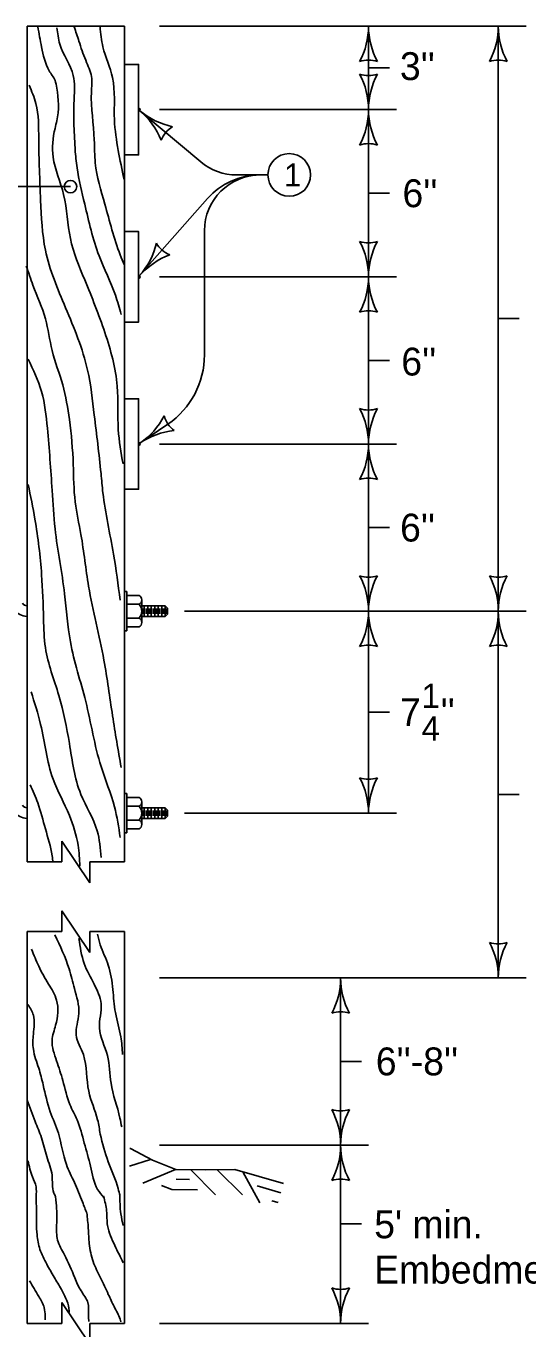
# Model space of a CAD drawing. Extents: x 228 to 3572, y -1307 to 1277.
# Drawn here: x 1403 to 1691, y -892 to -144 of the extents above; entities that cross this region are included whole.
import ezdxf

# ---------------------------------------------------------------- set-up
doc = ezdxf.new("R2010")
doc.units = 0
for name, color, linetype in [('dsnStdDimension', 7, 'Continuous'), ('Level 2', 7, 'Continuous'), ('Level 3', 7, 'Continuous')]:
    doc.layers.add(name, color=color, linetype=linetype)

msp = doc.modelspace()

# ---------------------------------------------------------------- linework, layer by layer
at = {"layer": 'dsnStdDimension'}
for p, q in [((1479.6, -143.79), (1690.1, -143.79)), ((1599.6, -143.79), (1599.6, -191.79)), ((1674.1, -143.79), (1674.1, -479.78)), ((1611.6, -167.79), (1599.6, -167.79)), ((1468.31, -192.38), (1503.31, -221.79)), ((1479.6, -191.79), (1615.6, -191.79)), ((1599.6, -191.79), (1599.6, -287.78)), ((1523.89, -229.29), (1541.87, -229.29)), ((1346.37, -235.99), (1428.56, -235.99)), ((1468.23, -287.06), (1507.17, -242.86)), ((1611.6, -239.79), (1599.6, -239.79)), ((1505.45, -261.29), (1505.45, -332.64)), ((1479.6, -287.78), (1615.6, -287.78)), ((1599.6, -287.78), (1599.6, -383.78)), ((1686.1, -311.78), (1674.1, -311.78)), ((1611.6, -335.78), (1599.6, -335.78)), ((1468.35, -383.27), (1484.44, -372.33)), ((1479.6, -383.78), (1615.6, -383.78)), ((1599.6, -383.78), (1599.6, -479.78)), ((1611.6, -431.78), (1599.6, -431.78)), ((1494.05, -479.78), (1690.1, -479.78)), ((1599.6, -479.78), (1599.6, -595.78)), ((1674.1, -479.78), (1674.1, -690.3)), ((1611.6, -537.78), (1599.6, -537.78)), ((1686.1, -585.04), (1674.1, -585.04)), ((1494.05, -595.78), (1615.6, -595.78)), ((1479.6, -690.3), (1690.1, -690.3)), ((1583.6, -690.3), (1583.6, -786.3)), ((1595.6, -738.3), (1583.6, -738.3)), ((1479.6, -786.3), (1599.6, -786.3)), ((1583.6, -786.3), (1583.6, -888.72)), ((1595.6, -831.51), (1583.6, -831.51)), ((1479.6, -888.72), (1599.6, -888.72))]:
    msp.add_line(p, q, dxfattribs=at)
msp.add_circle((1428.56, -235.99), 3.56, dxfattribs=at)
for centre, radius, start, end in [((1556.42, -143.79), 43.18, 331.92751, 0), ((1642.78, -143.79), 43.18, 180, 208.07249), ((1630.92, -143.79), 43.18, 331.92751, 0), ((1717.28, -143.79), 43.18, 180, 208.07249), ((1599.6, -179.99), 16.68, 72.26665, 107.73335), ((1674.1, -179.99), 16.68, 72.26665, 107.73335), ((1599.6, -155.58), 16.68, 252.26665, 287.73335), ((1556.42, -191.79), 43.18, 0, 28.07249), ((1642.78, -191.79), 43.18, 151.92751, 180), ((1496.08, -159.32), 43.18, 229.96145, 258.03394), ((1440.53, -225.44), 43.18, 21.88896, 49.96145), ((1556.42, -191.79), 43.18, 331.92751, 0), ((1642.78, -191.79), 43.18, 180, 208.07249), ((1496.03, -215.67), 16.68, 122.2281, 157.6948), ((1599.6, -227.99), 16.68, 72.26665, 107.73335), ((1523.9, -197.29), 32, 229.96456, 270), ((1537.45, -261.29), 32, 90, 180), ((1537.19, -269.29), 40, 90, 138.62574), ((1435.83, -258.52), 43.18, 318.62652, 346.69901), ((1492.16, -259.9), 16.68, 210.89317, 246.35987), ((1599.6, -251.58), 16.68, 252.26665, 287.73335), ((1556.42, -287.78), 43.18, 0, 28.07249), ((1642.78, -287.78), 43.18, 151.92751, 180), ((1500.63, -315.61), 43.18, 110.55403, 138.62652), ((1556.42, -287.78), 43.18, 331.92751, 0), ((1642.78, -287.78), 43.18, 180, 208.07249), ((1599.6, -323.99), 16.68, 72.26665, 107.73335), ((1457.45, -332.64), 48, 304.20895, 0), ((1599.6, -347.58), 16.68, 252.26665, 287.73335), ((1556.42, -383.78), 43.18, 0, 28.07249), ((1642.78, -383.78), 43.18, 151.92751, 180), ((1444.07, -347.57), 43.18, 304.20947, 332.28196), ((1498.29, -362.92), 16.68, 196.47612, 231.94282), ((1492.62, -418.98), 43.18, 96.13698, 124.20947), ((1556.42, -383.78), 43.18, 331.92751, 0), ((1642.78, -383.78), 43.18, 180, 208.07249), ((1599.6, -419.99), 16.68, 72.26665, 107.73335), ((1599.6, -443.58), 16.68, 252.26665, 287.73335), ((1556.42, -479.78), 43.18, 0, 28.07249), ((1642.78, -479.78), 43.18, 151.92751, 180), ((1674.1, -443.58), 16.68, 252.26665, 287.73335), ((1630.92, -479.78), 43.18, 0, 28.07249), ((1717.28, -479.78), 43.18, 151.92751, 180), ((1556.42, -479.78), 43.18, 331.92751, 0), ((1642.78, -479.78), 43.18, 180, 208.07249), ((1630.92, -479.78), 43.18, 331.92751, 0), ((1717.28, -479.78), 43.18, 180, 208.07249), ((1599.6, -515.99), 16.68, 72.26665, 107.73335), ((1674.1, -515.99), 16.68, 72.26665, 107.73335), ((1599.6, -559.58), 16.68, 252.26665, 287.73335), ((1556.42, -595.78), 43.18, 0, 28.07249), ((1642.78, -595.78), 43.18, 151.92751, 180), ((1674.1, -654.09), 16.68, 252.26665, 287.73335), ((1630.92, -690.3), 43.18, 0, 28.07249), ((1717.28, -690.3), 43.18, 151.92751, 180), ((1540.42, -690.3), 43.18, 331.92751, 0), ((1626.78, -690.3), 43.18, 180, 208.07249), ((1583.6, -726.51), 16.68, 72.26665, 107.73335), ((1583.6, -750.09), 16.68, 252.26665, 287.73335), ((1540.42, -786.3), 43.18, 0, 28.07249), ((1626.78, -786.3), 43.18, 151.92751, 180), ((1540.42, -786.3), 43.18, 331.92751, 0), ((1626.78, -786.3), 43.18, 180, 208.07249), ((1583.6, -822.51), 16.68, 72.26665, 107.73335), ((1583.6, -852.52), 16.68, 252.26665, 287.73335), ((1540.42, -888.72), 43.18, 0, 28.07249), ((1626.78, -888.72), 43.18, 151.92751, 180)]:
    msp.add_arc(centre, radius, start, end, dxfattribs=at)
at = {"layer": 'Level 2'}
for p, q in [((1403.6, -143.79), (1459.6, -143.79)), ((1403.6, -143.79), (1403.6, -623.78)), ((1459.6, -143.79), (1459.6, -623.78)), ((1459.6, -217.79), (1467.6, -217.79)), ((1459.6, -468.45), (1459.6, -491.12)), ((1460.93, -468.45), (1459.6, -468.45)), ((1460.93, -468.45), (1460.93, -491.12)), ((1460.93, -470.78), (1467.93, -470.78)), ((1403.59, -476.77), (1403.61, -482.8)), ((1460.93, -475.78), (1467.93, -475.78)), ((1469.43, -475.78), (1469.43, -473.28)), ((1469.43, -483.78), (1469.43, -475.78)), ((1469.43, -476.78), (1482.91, -476.78)), ((1469.91, -481.28), (1469.91, -478.28)), ((1470.91, -482.28), (1470.91, -477.28)), ((1471.91, -481.28), (1471.91, -478.28)), ((1472.91, -482.28), (1472.91, -477.28)), ((1473.91, -481.28), (1473.91, -478.28)), ((1474.91, -482.28), (1474.91, -477.28)), ((1475.91, -481.28), (1475.91, -478.28)), ((1476.91, -482.28), (1476.91, -477.28)), ((1477.91, -481.28), (1477.91, -478.28)), ((1478.91, -482.28), (1478.91, -477.28)), ((1479.91, -481.28), (1479.91, -478.28)), ((1480.91, -482.28), (1480.91, -477.28)), ((1481.91, -481.28), (1481.91, -478.28)), ((1482.91, -476.78), (1484.16, -478.03)), ((1482.91, -482.28), (1482.91, -477.28)), ((1483.91, -481.28), (1483.91, -478.28)), ((1484.16, -481.53), (1484.16, -478.03)), ((1460.93, -483.78), (1467.93, -483.78)), ((1469.43, -482.78), (1482.91, -482.78)), ((1469.43, -486.28), (1469.43, -483.78)), ((1482.91, -482.78), (1484.16, -481.53)), ((1460.93, -491.12), (1459.6, -491.12)), ((1460.93, -488.78), (1467.93, -488.78)), ((1459.6, -584.45), (1459.6, -607.12)), ((1460.93, -584.45), (1459.6, -584.45)), ((1460.93, -584.45), (1460.93, -607.12)), ((1460.93, -586.78), (1467.93, -586.78)), ((1469.43, -591.78), (1469.43, -589.28)), ((1460.93, -591.78), (1467.93, -591.78)), ((1469.43, -599.78), (1469.43, -591.78)), ((1469.43, -592.78), (1482.91, -592.78)), ((1469.91, -597.28), (1469.91, -594.28)), ((1470.91, -598.28), (1470.91, -593.28)), ((1471.91, -597.28), (1471.91, -594.28)), ((1472.91, -598.28), (1472.91, -593.28)), ((1473.91, -597.28), (1473.91, -594.28)), ((1474.91, -598.28), (1474.91, -593.28)), ((1475.91, -597.28), (1475.91, -594.28)), ((1476.91, -598.28), (1476.91, -593.28)), ((1477.91, -597.28), (1477.91, -594.28)), ((1478.91, -598.28), (1478.91, -593.28)), ((1479.91, -597.28), (1479.91, -594.28)), ((1480.91, -598.28), (1480.91, -593.28)), ((1481.91, -597.28), (1481.91, -594.28)), ((1482.91, -592.78), (1484.16, -594.03)), ((1482.91, -598.28), (1482.91, -593.28)), ((1482.91, -598.78), (1484.16, -597.53)), ((1483.91, -597.28), (1483.91, -594.28)), ((1484.16, -597.53), (1484.16, -594.03)), ((1460.93, -599.78), (1467.93, -599.78)), ((1460.93, -604.78), (1467.93, -604.78)), ((1469.43, -598.78), (1482.91, -598.78)), ((1469.43, -602.28), (1469.43, -599.78)), ((1423.6, -623.78), (1423.6, -611.78)), ((1439.6, -635.78), (1423.6, -611.78)), ((1460.93, -607.12), (1459.6, -607.12)), ((1423.6, -623.78), (1403.6, -623.78)), ((1439.6, -623.78), (1439.6, -635.78)), ((1459.6, -623.78), (1439.6, -623.78)), ((1423.6, -663.78), (1423.6, -651.78)), ((1439.6, -675.78), (1423.6, -651.78)), ((1403.6, -663.78), (1403.6, -816.25)), ((1423.6, -663.78), (1403.6, -663.78)), ((1439.6, -663.78), (1439.6, -675.78)), ((1459.6, -663.78), (1439.6, -663.78)), ((1459.6, -663.78), (1459.6, -816.25)), ((1474.39, -794.68), (1462.37, -798.41)), ((1488.73, -800.31), (1470.05, -808.31)), ((1497.49, -800.43), (1511.77, -814.89)), ((1512.89, -800.67), (1527.34, -814.96)), ((1527.44, -801.68), (1537.3, -819.45)), ((1403.6, -816.25), (1403.6, -888.72)), ((1459.6, -816.25), (1459.6, -888.72)), ((1423.6, -888.72), (1423.6, -876.72)), ((1439.6, -900.72), (1423.6, -876.72)), ((1423.6, -888.72), (1403.6, -888.72)), ((1439.6, -888.72), (1439.6, -900.72)), ((1459.6, -888.72), (1439.6, -888.72))]:
    msp.add_line(p, q, dxfattribs=at)
for points in [[(1459.6, -165.79), (1467.6, -165.79), (1467.6, -217.79), (1459.6, -217.79)], [(1459.6, -261.78), (1467.6, -261.78), (1467.6, -313.78), (1459.6, -313.78)], [(1459.6, -357.78), (1467.6, -357.78), (1467.6, -409.78), (1459.6, -409.78)]]:
    msp.add_lwpolyline(points, close=True, dxfattribs=at)
for points in [[(1462.67, -788.22), (1462.91, -788.38), (1475.61, -795.06), (1488.91, -800.38), (1505.91, -800.48), (1522.9, -800.38), (1536.89, -804.39), (1550.89, -808.39)], [(1489.21, -805.97), (1496.94, -806.02)], [(1489.21, -805.97), (1496.94, -806.02)], [(1480.72, -809.53), (1486.65, -811.91), (1501.43, -811.99)], [(1480.72, -809.53), (1486.65, -811.91), (1501.43, -811.99)], [(1535.67, -809.82), (1549.36, -813.74)], [(1544.03, -818.34), (1547.74, -819.4)]]:
    msp.add_lwpolyline(points, dxfattribs=at)
msp.add_circle((1554.12, -229.29), 12.25, dxfattribs=at)
for centre, radius, start, end in [((1466.6, -473.28), 2.83, 298.07249, 61.92751), ((1404.12, -472.78), 4.02, 217.44554, 262.43895), ((1463.35, -479.78), 6.08, 318.88791, 41.11209), ((1404.12, -472.78), 10.04, 217.30891, 267.0982), ((1466.6, -486.28), 2.83, 298.07249, 61.92751), ((1466.6, -589.28), 2.83, 298.07249, 61.92751), ((1404.12, -588.78), 10.04, 217.30891, 267.0982), ((1404.12, -588.78), 4.02, 217.44554, 262.43895), ((1463.35, -595.78), 6.08, 318.88791, 41.11209), ((1466.6, -602.28), 2.83, 298.07249, 61.92751)]:
    msp.add_arc(centre, radius, start, end, dxfattribs=at)
for points in [[(1409.75, -144.19), (1411.95, -155.76), (1416.35, -169.52), (1419.65, -175.03), (1420.75, -179.43), (1420.75, -198.15), (1419.65, -202.55), (1418.55, -219.07), (1424.61, -240.54), (1428.46, -265.86), (1436.71, -289.54), (1448.26, -319.82), (1455.41, -350.65), (1455.96, -375.42), (1458.71, -395.24)], [(1420.75, -144.75), (1422.41, -154.1), (1430.11, -172.27), (1430.66, -185.49), (1431.21, -214.67), (1432.31, -225.13), (1436.71, -246.05), (1444.96, -275.77), (1454.31, -298.35), (1457.61, -309.36)], [(1430.66, -144.19), (1433.41, -152.45), (1437.26, -163.46), (1440.56, -172.82), (1440.56, -181.63), (1442.21, -209.16), (1442.76, -222.37), (1448.26, -246.05), (1457.06, -275.22), (1459.26, -280.73)], [(1445.51, -144.19), (1447.16, -155.76), (1452.66, -173.37), (1453.76, -197.6), (1455.96, -215.22), (1459.26, -231.73)], [(1404.8, -177.78), (1408.65, -188.24), (1410.3, -208.61), (1411.4, -243.84), (1414.15, -272.47), (1425.71, -305.5), (1438.36, -341.29), (1442.21, -367.16), (1446.06, -400.75), (1447.16, -411.76), (1453.21, -446.99), (1457.06, -473.42)], [(1403.16, -281.59), (1407.01, -292.6), (1414.16, -311.87), (1418.01, -330.04), (1424.06, -349.86), (1427.92, -369.68), (1430.12, -395.56), (1431.22, -417.03), (1434.52, -435.75), (1438.92, -465.48), (1447.72, -507.87), (1452.67, -539.8), (1457.62, -569.53)], [(1404.26, -335), (1411.96, -353.72), (1415.26, -374.64), (1418.01, -410.42), (1419.66, -432.44), (1425.17, -469.88), (1428.47, -497.41), (1437.27, -531.54), (1446.07, -568.98), (1453.77, -592.1), (1457.07, -609.72)], [(1404.26, -407.12), (1408.11, -426.94), (1411.96, -458.87), (1413.06, -484.2), (1414.16, -500.71), (1421.86, -528.24), (1427.92, -555.77), (1434.52, -584.95), (1443.87, -605.87), (1446.07, -621.28)], [(1405.91, -526.04), (1411.41, -544.76), (1418.56, -576.14), (1427.92, -597.06), (1432.87, -614.12), (1433.97, -626.24)], [(1405.36, -579.44), (1409.76, -589.9), (1414.16, -604.77), (1418.01, -620.18), (1418.56, -624.03)], [(1419.52, -665.69), (1427.72, -685.17), (1430.79, -696.46), (1433.35, -710.82), (1431.82, -723.12), (1435.92, -734.41), (1438.99, -755.43), (1444.11, -771.84), (1445.65, -780.05), (1450.26, -795.94), (1455.9, -811.33), (1456.92, -815.43)], [(1444.11, -665.18), (1445.65, -671.33), (1450.26, -683.12), (1452.82, -696.97), (1454.36, -710.3), (1457.44, -724.15), (1458.46, -734.41)], [(1433.35, -667.74), (1436.43, -682.1), (1442.06, -693.89), (1446.16, -705.17), (1445.14, -719.02), (1449.75, -734.92), (1451.8, -750.82), (1456.92, -770.82), (1457.95, -775.94)], [(1406.2, -673.89), (1410.3, -683.64), (1415.93, -693.89), (1420.54, -703.12), (1420.03, -717.48), (1417.98, -726.2), (1420.54, -738), (1424.13, -749.28), (1428.23, -763.12), (1432.33, -771.84), (1436.43, -785.17), (1440.02, -798.51), (1444.11, -811.84), (1447.7, -816.46)], [(1404.15, -705.69), (1407.22, -711.84), (1407.22, -722.61), (1407.22, -731.33), (1410.3, -742.1), (1412.86, -751.84), (1416.96, -767.23), (1421.57, -779.53), (1426.18, -797.48), (1430.79, -807.74), (1435.4, -819.02), (1437.97, -825.69)], [(1403.64, -760.56), (1408.25, -772.87), (1411.83, -782.1), (1414.91, -792.87), (1417.98, -803.64), (1419.01, -813.89), (1420.03, -815.94)], [(1404.15, -795.43), (1406.71, -804.66), (1408.76, -810.3), (1408.76, -815.94)], [(1456.88, -814.57), (1457.44, -825.78), (1458.84, -832.6)], [(1408.76, -815.94), (1409.04, -824.36), (1409.32, -837.81), (1411, -846.22), (1414.92, -854.64), (1419.13, -862.21), (1423.33, -869.22), (1426.41, -875.66), (1427.81, -881.55), (1427.81, -882.21)], [(1420.03, -815.94), (1420.59, -822.95), (1420.59, -832.21), (1421.15, -840.9), (1425.07, -849.31), (1430.96, -862.49), (1434.6, -870.06), (1438.52, -876.78), (1438.8, -884.07), (1439.08, -887.72)], [(1447.56, -815.74), (1449.24, -824.15), (1449.8, -832.56), (1454, -844.06), (1458.79, -853.92)], [(1437.92, -825.24), (1438.76, -834.21), (1439.32, -842.9), (1441.57, -853.27), (1445.77, -862.53), (1450.25, -872.06), (1453.61, -879.07), (1456.97, -886.36), (1457.37, -887.9)], [(1405.03, -864.27), (1410.35, -873.24), (1413.44, -879.69), (1414, -884.45), (1414, -886.7)]]:
    msp.add_spline(points, degree=3, dxfattribs=at)
at = {"layer": 'Level 3'}
for centre in [(1467.19, -191.79), (1467.19, -287.78), (1467.19, -383.78)]:
    msp.add_arc(centre, 1.27, 288.87046, 71.12954, dxfattribs=at)

# ---------------------------------------------------------------- texts
at = {"layer": 'dsnStdDimension'}
for s, height, p in [("3''", 16, (1617.63, -174.81)), ("6''", 16, (1619.1, -247.79)), ("6''", 16, (1618.42, -344.45)), ("6''", 16, (1617.73, -439.78)), ('1', 14, (1630.1, -535.41)), ('7', 16, (1617.68, -545.74)), ("''", 16, (1640.98, -545.74)), ('4', 14, (1630.1, -554.08)), ("6''-8''", 16, (1603.79, -746.3)), ("5' min.", 16, (1602.88, -839.87)), ('Embedment', 16, (1602.88, -865.87))]:
    msp.add_text(s, height=height, dxfattribs=at).set_placement(p)
at = {"layer": 'Level 2'}
msp.add_text('1', height=13.2, dxfattribs=at).set_placement((1551.18, -235.89))

doc.saveas('drawing.dxf')
